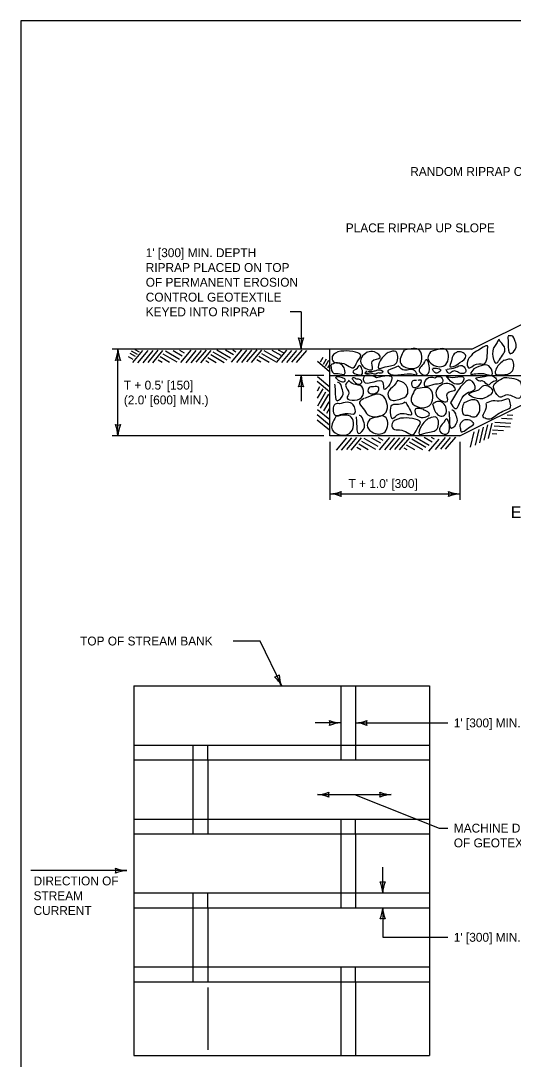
# Model space of a CAD drawing. Extents: x 49991.4 to 50021, y 49987.6 to 50011.4.
# Drawn here: x 50000.34 to 50003.67, y 50004.24 to 50011.26 of the extents above; entities that cross this region are included whole.
import ezdxf

# ---------------------------------------------------------------- set-up
doc = ezdxf.new("R2010")
doc.units = 0
for name, color, linetype in [('Level 1', 7, 'Continuous'), ('Level 2', 7, 'Continuous'), ('Level 3', 7, 'Continuous'), ('Level 4', 7, 'Continuous')]:
    doc.layers.add(name, color=color, linetype=linetype)

msp = doc.modelspace()

# ---------------------------------------------------------------- linework, layer by layer
at = {"layer": 'Level 1'}
for p, q in [((50003.3042, 50008.4558), (50006.7558, 50010.1815)), ((50003.3845, 50009.0417), (50005.7004, 50010.1996)), ((50003.6281, 50009.1282), (50003.6283, 50009.1231)), ((50003.6482, 50009.1332), (50003.6298, 50009.1332)), ((50003.3845, 50009.0417), (50000.9525, 50009.0417)), ((50001.1249, 50009.0062), (50001.0844, 50009.0296)), ((50001.0925, 50008.9516), (50001.1616, 50009.034)), ((50001.1375, 50009.0226), (50001.1098, 50009.0386)), ((50001.128, 50008.9503), (50001.1972, 50009.0327)), ((50001.162, 50008.9503), (50001.2313, 50009.0327)), ((50001.1961, 50008.9528), (50001.2653, 50009.0355)), ((50001.2274, 50008.9503), (50001.2968, 50009.0327)), ((50001.4086, 50008.9731), (50001.314, 50009.0278)), ((50001.4276, 50008.9957), (50001.3667, 50009.0309)), ((50001.4436, 50009.0149), (50001.411, 50009.0336)), ((50001.4176, 50008.952), (50001.487, 50009.0344)), ((50001.4531, 50008.9507), (50001.5225, 50009.0332)), ((50001.4874, 50008.9507), (50001.5565, 50009.0332)), ((50001.5214, 50008.9534), (50001.5905, 50009.0358)), ((50001.5528, 50008.9507), (50001.6219, 50009.0332)), ((50001.7307, 50008.9679), (50001.6359, 50009.0226)), ((50001.7543, 50008.9809), (50001.6616, 50009.0344)), ((50001.7733, 50009.0036), (50001.7198, 50009.0344)), ((50001.7602, 50008.9542), (50001.8293, 50009.0366)), ((50001.7893, 50009.0227), (50001.7688, 50009.0344)), ((50001.7957, 50008.9528), (50001.8648, 50009.0355)), ((50001.8297, 50008.9528), (50001.8988, 50009.0355)), ((50001.8637, 50008.9555), (50001.9331, 50009.0379)), ((50001.8952, 50008.9528), (50001.9644, 50009.0355)), ((50002.0764, 50008.9757), (50001.9816, 50009.0304)), ((50002.0953, 50008.9983), (50002.0342, 50009.0336)), ((50002.0643, 50008.9524), (50002.1334, 50009.0348)), ((50002.1113, 50009.0175), (50002.0788, 50009.0362)), ((50002.0999, 50008.9511), (50002.169, 50009.0336)), ((50002.1338, 50008.9511), (50002.203, 50009.0336)), ((50002.1678, 50008.9538), (50002.2371, 50009.0362)), ((50002.1992, 50008.9511), (50002.2686, 50009.0336)), ((50002.4254, 50008.8642), (50002.4254, 50009.0417)), ((50003.556, 50009.0864), (50003.5296, 50009.046)), ((50001.0954, 50008.9715), (50001.064, 50008.9898)), ((50001.111, 50008.9922), (50001.0749, 50009.0132)), ((50001.2914, 50008.9516), (50001.2637, 50008.9675)), ((50001.3421, 50008.9519), (50001.2776, 50008.9891)), ((50001.3926, 50008.9542), (50001.298, 50009.0089)), ((50001.6061, 50008.9507), (50001.5858, 50008.9624)), ((50001.6573, 50008.9507), (50001.5996, 50008.9839)), ((50001.7117, 50008.9507), (50001.6199, 50009.0036)), ((50001.9592, 50008.9542), (50001.9315, 50008.9702)), ((50002.0148, 50008.9515), (50001.9453, 50008.9917)), ((50002.0604, 50008.9567), (50001.9656, 50009.0114)), ((50002.3415, 50008.9599), (50002.4239, 50008.8908)), ((50002.3614, 50008.957), (50002.3797, 50008.9884)), ((50002.3821, 50008.9414), (50002.4031, 50008.9775)), ((50002.3961, 50008.9275), (50002.4195, 50008.968)), ((50003.389, 50009.0094), (50003.3812, 50008.9977)), ((50002.4125, 50008.9149), (50002.4254, 50008.9372)), ((50002.3402, 50008.825), (50002.4226, 50008.7556)), ((50002.3427, 50008.8563), (50002.4254, 50008.7871)), ((50002.4254, 50008.4558), (50002.4254, 50008.8642)), ((50002.3415, 50008.761), (50002.3574, 50008.7887)), ((50002.3418, 50008.7103), (50002.379, 50008.7748)), ((50002.3441, 50008.6598), (50002.3988, 50008.7544)), ((50003.2877, 50008.7575), (50003.2405, 50008.679)), ((50002.363, 50008.6438), (50002.4177, 50008.7384)), ((50002.3856, 50008.6248), (50002.4208, 50008.6857)), ((50002.3419, 50008.6348), (50002.4243, 50008.5654)), ((50002.4048, 50008.6088), (50002.4235, 50008.6414)), ((50002.3406, 50008.5993), (50002.4231, 50008.5299)), ((50002.3406, 50008.565), (50002.4231, 50008.4959)), ((50003.4689, 50008.4262), (50003.4939, 50008.5312)), ((50003.4982, 50008.438), (50003.5232, 50008.5426)), ((50003.65, 50008.5395), (50003.5408, 50008.546)), ((50003.6568, 50008.5683), (50003.5865, 50008.5726)), ((50003.6626, 50008.5925), (50003.6251, 50008.5949)), ((50003.3767, 50008.3789), (50003.4019, 50008.4835)), ((50003.4091, 50008.3937), (50003.4341, 50008.4984)), ((50003.4396, 50008.4087), (50003.4646, 50008.5136)), ((50003.5548, 50008.4679), (50003.5228, 50008.4699)), ((50003.6, 50008.4907), (50003.5255, 50008.4953)), ((50003.6442, 50008.5153), (50003.5352, 50008.5219)), ((50003.3042, 50008.4558), (50002.4254, 50008.4558)), ((50002.4711, 50008.3601), (50002.5402, 50008.4425)), ((50002.505, 50008.3601), (50002.5744, 50008.4425)), ((50002.5393, 50008.3626), (50002.6084, 50008.445)), ((50002.5705, 50008.3601), (50002.6398, 50008.4425)), ((50002.6851, 50008.3617), (50002.6207, 50008.3989)), ((50002.7357, 50008.364), (50002.641, 50008.4187)), ((50002.7518, 50008.3829), (50002.657, 50008.4376)), ((50002.7706, 50008.4055), (50002.7097, 50008.4407)), ((50002.7867, 50008.4247), (50002.7541, 50008.4434)), ((50002.7607, 50008.3618), (50002.83, 50008.4442)), ((50002.7963, 50008.3605), (50002.8656, 50008.443)), ((50002.8304, 50008.3605), (50002.8995, 50008.443)), ((50002.8644, 50008.3632), (50002.9335, 50008.4456)), ((50002.8959, 50008.3605), (50002.965, 50008.443)), ((50003.0003, 50008.3605), (50002.9428, 50008.3937)), ((50003.0549, 50008.3605), (50002.9631, 50008.4134)), ((50003.0737, 50008.3777), (50002.9791, 50008.4324)), ((50003.0974, 50008.3907), (50003.0046, 50008.4442)), ((50003.1163, 50008.4134), (50003.0628, 50008.4442)), ((50003.1624, 50008.4341), (50003.0933, 50008.3516)), ((50003.1323, 50008.4325), (50003.1119, 50008.4442)), ((50003.1388, 50008.3626), (50003.208, 50008.445)), ((50003.1749, 50008.3653), (50003.242, 50008.445)), ((50003.2068, 50008.3653), (50003.2761, 50008.4477)), ((50002.6346, 50008.3613), (50002.6069, 50008.3773)), ((50002.9491, 50008.3605), (50002.9288, 50008.3722)), ((50001.0997, 50006.7648), (50003.0997, 50006.7648)), ((50001.0997, 50006.7648), (50001.0997, 50004.2648)), ((50002.5997, 50006.7648), (50002.5997, 50006.2648)), ((50003.0997, 50006.7648), (50003.0997, 50004.2648)), ((50001.0997, 50006.2648), (50003.0997, 50006.2648)), ((50001.5997, 50006.2648), (50001.5997, 50005.7648)), ((50001.0997, 50005.7648), (50003.0997, 50005.7648)), ((50002.5997, 50005.7648), (50002.5997, 50005.2648)), ((50001.0997, 50005.2648), (50003.0997, 50005.2648)), ((50001.5997, 50005.2648), (50001.5997, 50004.7648)), ((50001.0997, 50004.7648), (50003.0997, 50004.7648)), ((50002.5997, 50004.7648), (50002.5997, 50004.2648)), ((50001.0997, 50004.2648), (50003.0997, 50004.2648))]:
    msp.add_line(p, q, dxfattribs=at)
msp.add_lwpolyline([(50008.6146, 50011.2628), (50000.3356, 50011.2628), (50000.3356, 50000.0624), (50008.6146, 50000.0624)], close=True, dxfattribs=at)
msp.add_lwpolyline([(50002.4254, 50008.8642), (50004.0986, 50008.8642), (50004.0986, 50008.8642)], dxfattribs=at)
for points in [[(50003.5284, 50009.0453), (50003.5322, 50008.9714), (50003.5485, 50008.9477), (50003.5719, 50008.9707), (50003.609, 50009.0442), (50003.5754, 50009.0964)], [(50003.5754, 50009.0964), (50003.5689, 50009.1065), (50003.556, 50009.0864)], [(50003.6283, 50009.1231), (50003.6314, 50009.0797), (50003.6447, 50009.0112), (50003.6849, 50009.0547), (50003.6781, 50009.0948), (50003.6533, 50009.1332), (50003.6482, 50009.1332)], [(50002.4994, 50009.0288), (50002.442, 50008.9918), (50002.4498, 50008.9567), (50002.4936, 50008.9499), (50002.5455, 50008.9312), (50002.5832, 50008.9167), (50002.6109, 50008.9571), (50002.6342, 50009.002), (50002.5803, 50009.0262), (50002.5006, 50009.0288)], [(50002.6777, 50009.0211), (50002.6397, 50008.986), (50002.6408, 50008.9362), (50002.7128, 50008.9079), (50002.7111, 50008.9606), (50002.7658, 50008.9848), (50002.7264, 50009.0235), (50002.6789, 50009.0219)], [(50002.8199, 50009.0214), (50002.7663, 50008.9641), (50002.7541, 50008.9133), (50002.8003, 50008.9218), (50002.8756, 50008.9496), (50002.8706, 50009.0262), (50002.8222, 50009.02)], [(50002.9287, 50009.0356), (50002.9042, 50008.9452), (50003.0226, 50008.9233), (50003.0334, 50009.0319), (50002.9299, 50009.036)], [(50003.1068, 50009.0237), (50003.0886, 50008.9829), (50003.1201, 50008.9382), (50003.2093, 50008.9387), (50003.2171, 50009.0335), (50003.1068, 50009.0241)], [(50003.2892, 50009.0254), (50003.2605, 50009.0043), (50003.2472, 50008.9624), (50003.2396, 50008.9222), (50003.2585, 50008.9241), (50003.3046, 50008.9508), (50003.3447, 50008.9968), (50003.3275, 50009.0179), (50003.2892, 50009.0235)], [(50003.3812, 50008.9977), (50003.3558, 50008.9594), (50003.3624, 50008.9161), (50003.4159, 50008.9411), (50003.4728, 50008.9444), (50003.4893, 50008.9995), (50003.4925, 50009.0542)], [(50003.4925, 50009.0542), (50003.4927, 50009.0581), (50003.4308, 50009.0364), (50003.3877, 50009.0094)], [(50002.4318, 50008.9347), (50002.4525, 50008.8783), (50002.481, 50008.8779), (50002.5242, 50008.8725), (50002.5104, 50008.9322), (50002.4655, 50008.9494), (50002.4337, 50008.9353)], [(50003.0635, 50008.9496), (50003.0322, 50008.8883), (50003.0752, 50008.8663), (50003.0982, 50008.9047), (50003.0752, 50008.9694), (50003.0612, 50008.9496)], [(50003.6041, 50008.9679), (50003.5508, 50008.9106), (50003.5451, 50008.8754), (50003.5845, 50008.8683), (50003.6598, 50008.8961), (50003.6548, 50008.9727), (50003.6067, 50008.9664)], [(50002.6121, 50008.9114), (50002.5808, 50008.8878), (50002.6147, 50008.87), (50002.6426, 50008.8711), (50002.6238, 50008.9312), (50002.61, 50008.9114)], [(50002.7412, 50008.8508), (50002.6597, 50008.859), (50002.6568, 50008.8202), (50002.7861, 50008.8157), (50002.7925, 50008.7723), (50002.8449, 50008.8434), (50002.7412, 50008.8508)], [(50002.682, 50008.893), (50002.7212, 50008.893), (50002.7433, 50008.9004), (50002.772, 50008.9004), (50002.7836, 50008.8892), (50002.7786, 50008.881), (50002.7541, 50008.881), (50002.7301, 50008.8725), (50002.7068, 50008.8783), (50002.6867, 50008.8783), (50002.6649, 50008.8783), (50002.6758, 50008.895)], [(50002.8874, 50008.9278), (50002.832, 50008.905), (50002.8167, 50008.8954), (50002.8225, 50008.8819), (50002.8644, 50008.8667), (50002.9473, 50008.8752), (50002.989, 50008.8729), (50003.0139, 50008.8687), (50003.0003, 50008.8954), (50002.9296, 50008.8993), (50002.8874, 50008.9261)], [(50003.1208, 50008.9132), (50003.146, 50008.9132), (50003.1747, 50008.9), (50003.1619, 50008.8876), (50003.1479, 50008.8795), (50003.1258, 50008.8934), (50003.1196, 50008.9101)], [(50003.2185, 50008.9078), (50003.2751, 50008.9186), (50003.3194, 50008.931), (50003.3419, 50008.9078), (50003.3419, 50008.8861), (50003.3108, 50008.8775), (50003.2821, 50008.8915), (50003.2534, 50008.8915), (50003.2333, 50008.8775), (50003.2123, 50008.9047)], [(50003.3995, 50008.9089), (50003.3772, 50008.8767), (50003.4528, 50008.8783), (50003.5224, 50008.869), (50003.5099, 50008.9187), (50003.3995, 50008.9094)], [(50002.4576, 50008.8058), (50002.4608, 50008.7622), (50002.474, 50008.6937), (50002.5143, 50008.7372), (50002.5074, 50008.7773), (50002.4826, 50008.8157), (50002.4776, 50008.8157)], [(50002.4667, 50008.8473), (50002.5022, 50008.8226), (50002.5286, 50008.8265), (50002.5286, 50008.8362), (50002.5098, 50008.8488), (50002.4731, 50008.8539), (50002.4638, 50008.8508), (50002.4638, 50008.8467)], [(50002.551, 50008.8265), (50002.5319, 50008.7977), (50002.5527, 50008.7442), (50002.5414, 50008.7118), (50002.5929, 50008.6964), (50002.6484, 50008.729), (50002.6408, 50008.7902), (50002.5873, 50008.8055), (50002.551, 50008.8323)], [(50002.5747, 50008.8447), (50002.599, 50008.8143), (50002.6289, 50008.8061), (50002.6419, 50008.8217), (50002.6263, 50008.8376), (50002.6019, 50008.842), (50002.5901, 50008.8486), (50002.5751, 50008.8457)], [(50002.8838, 50008.8323), (50002.8607, 50008.796), (50002.8187, 50008.7501), (50002.8303, 50008.7042), (50002.901, 50008.7042), (50002.9488, 50008.7347), (50002.9353, 50008.8055), (50002.8857, 50008.8304)], [(50003.01, 50008.8304), (50002.9812, 50008.8227), (50002.9851, 50008.7882), (50003.0271, 50008.7941), (50003.0425, 50008.8323), (50003.0195, 50008.8304)], [(50003.1359, 50008.8492), (50003.08, 50008.8417), (50003.0679, 50008.7909), (50003.114, 50008.7993), (50003.1892, 50008.8274), (50003.1753, 50008.8554), (50003.1359, 50008.8492)], [(50003.1865, 50008.805), (50003.1484, 50008.7698), (50003.1495, 50008.72), (50003.2217, 50008.6917), (50003.2198, 50008.7445), (50003.2745, 50008.7687), (50003.2351, 50008.8075), (50003.1877, 50008.8058)], [(50003.2132, 50008.857), (50003.2202, 50008.85), (50003.2659, 50008.8086), (50003.3271, 50008.8253), (50003.3298, 50008.8515), (50003.2717, 50008.8519), (50003.2132, 50008.857)], [(50003.2409, 50008.6781), (50003.273, 50008.6399), (50003.3447, 50008.7407), (50003.4076, 50008.7747), (50003.3749, 50008.8316), (50003.3179, 50008.7964), (50003.2877, 50008.7589)], [(50003.4117, 50008.8488), (50003.4714, 50008.857), (50003.5393, 50008.8531), (50003.5513, 50008.8314), (50003.5242, 50008.8197), (50003.497, 50008.7988), (50003.4605, 50008.8263), (50003.4392, 50008.8263), (50003.4097, 50008.8453)], [(50003.6037, 50008.8507), (50003.5322, 50008.7883), (50003.5552, 50008.736), (50003.5758, 50008.7179), (50003.6123, 50008.7308), (50003.6613, 50008.7222), (50003.7082, 50008.7113), (50003.7212, 50008.7524), (50003.7141, 50008.8179), (50003.6037, 50008.8507)], [(50002.6561, 50008.7079), (50002.6256, 50008.6831), (50002.6503, 50008.6409), (50002.6828, 50008.5989), (50002.8053, 50008.6161), (50002.7785, 50008.729), (50002.66, 50008.7079)], [(50002.7174, 50008.7882), (50002.6906, 50008.7825), (50002.6847, 50008.7538), (50002.7537, 50008.7597), (50002.7537, 50008.7844), (50002.721, 50008.7882)], [(50003.0033, 50008.7715), (50002.9788, 50008.6812), (50003.0972, 50008.6593), (50003.108, 50008.7679), (50003.0045, 50008.7719)], [(50003.4052, 50008.7579), (50003.3647, 50008.7359), (50003.4022, 50008.7136), (50003.4741, 50008.7122), (50003.5244, 50008.7649), (50003.4673, 50008.7965), (50003.4327, 50008.7676), (50003.4052, 50008.7579)], [(50002.4897, 50008.6735), (50002.4609, 50008.6696), (50002.4592, 50008.5969), (50002.528, 50008.6066), (50002.5949, 50008.6085), (50002.5834, 50008.6659), (50002.4878, 50008.6715)], [(50002.9334, 50008.6831), (50002.8894, 50008.6676), (50002.8455, 50008.664), (50002.8494, 50008.5742), (50002.8913, 50008.6027), (50002.9756, 50008.5989), (50002.9393, 50008.6831)], [(50003.1193, 50008.6727), (50003.14, 50008.6163), (50003.1685, 50008.5915), (50003.2002, 50008.5952), (50003.1982, 50008.6704), (50003.1533, 50008.6874), (50003.1213, 50008.6735)], [(50003.2405, 50008.679), (50003.2404, 50008.6788), (50003.2409, 50008.6781)], [(50003.3315, 50008.68), (50003.3206, 50008.6382), (50003.3341, 50008.5969), (50003.3577, 50008.5958), (50003.3888, 50008.5843), (50003.4194, 50008.5921), (50003.4228, 50008.6926), (50003.3304, 50008.6788)], [(50003.4795, 50008.6754), (50003.4759, 50008.627), (50003.4624, 50008.5817), (50003.4667, 50008.5804)], [(50003.6455, 50008.6691), (50003.6348, 50008.7038), (50003.5863, 50008.6921), (50003.5276, 50008.6921), (50003.481, 50008.6773)], [(50002.4658, 50008.586), (50002.4414, 50008.4956), (50002.5597, 50008.4738), (50002.5705, 50008.5824), (50002.467, 50008.5864)], [(50002.6956, 50008.5684), (50002.6773, 50008.5277), (50002.7088, 50008.4829), (50002.7982, 50008.4835), (50002.8061, 50008.5782), (50002.6956, 50008.5688)], [(50003.0597, 50008.6333), (50003.0023, 50008.6352), (50003.0175, 50008.5894), (50003.0999, 50008.6027), (50003.0577, 50008.6313)], [(50003.2304, 50008.6202), (50003.2335, 50008.5766), (50003.2468, 50008.5081), (50003.287, 50008.5516), (50003.2802, 50008.5917), (50003.2552, 50008.6301), (50003.2503, 50008.6301)], [(50003.4667, 50008.5804), (50003.4975, 50008.5704), (50003.583, 50008.6169), (50003.6481, 50008.6605), (50003.6455, 50008.6691)], [(50002.6031, 50008.5837), (50002.6062, 50008.5403), (50002.6194, 50008.4718), (50002.6596, 50008.5153), (50002.6527, 50008.5554), (50002.6279, 50008.5938), (50002.623, 50008.5938)], [(50002.9031, 50008.5755), (50002.8456, 50008.5386), (50002.8535, 50008.5035), (50002.8972, 50008.4966), (50002.9491, 50008.4778), (50002.9869, 50008.4634), (50003.0146, 50008.5038), (50003.0378, 50008.5488), (50002.9839, 50008.573), (50002.9042, 50008.5755)], [(50003.0952, 50008.5757), (50003.0417, 50008.5184), (50003.0296, 50008.4676), (50003.0757, 50008.4761), (50003.151, 50008.504), (50003.146, 50008.5805), (50003.0976, 50008.5743)], [(50003.1994, 50008.5499), (50003.1681, 50008.4886), (50003.2111, 50008.4665), (50003.2339, 50008.505), (50003.2111, 50008.5696), (50003.1972, 50008.5499)], [(50003.3373, 50008.5652), (50003.3056, 50008.5352), (50003.3092, 50008.5024)], [(50003.3092, 50008.5024), (50003.3107, 50008.4884), (50003.3741, 50008.5169), (50003.3959, 50008.5434), (50003.3944, 50008.5446)], [(50003.3944, 50008.5446), (50003.3791, 50008.5587), (50003.3408, 50008.5652)]]:
    msp.add_spline(points, degree=3, dxfattribs=at)
at = {"layer": 'Level 3'}
for p, q in [((50002.2307, 50009.2943), (50002.1578, 50009.2943)), ((50002.2307, 50009.2943), (50002.2307, 50009.0417)), ((50000.9925, 50008.4558), (50000.9925, 50009.0417)), ((50002.3854, 50008.8642), (50002.1907, 50008.8642)), ((50002.2307, 50008.8642), (50002.2307, 50008.6907)), ((50002.3854, 50008.4558), (50000.9525, 50008.4558)), ((50002.4254, 50008.4158), (50002.4254, 50008.0234)), ((50003.3042, 50008.4158), (50003.3042, 50008.0234)), ((50002.4254, 50008.0634), (50003.3042, 50008.0634)), ((50001.9542, 50007.0683), (50001.7711, 50007.0683)), ((50002.0997, 50006.7648), (50001.9542, 50007.0683)), ((50002.4997, 50006.5148), (50002.3262, 50006.5148)), ((50002.5997, 50006.5148), (50003.2233, 50006.5148)), ((50002.3428, 50006.0297), (50002.8393, 50006.0297)), ((50002.591, 50006.0297), (50003.1651, 50005.8032)), ((50003.1651, 50005.8032), (50003.2233, 50005.8032)), ((50001.0526, 50005.5159), (50000.404, 50005.5159)), ((50002.7825, 50005.3648), (50002.7825, 50005.5382)), ((50002.7825, 50005.2648), (50002.7825, 50005.0648)), ((50002.7825, 50005.0648), (50003.2233, 50005.0648)), ((50001.5997, 50004.7248), (50001.5997, 50004.3048))]:
    msp.add_line(p, q, dxfattribs=at)
for centre, radius, start, end in [((50002.2307, 50009.1699), 0.0548, 252.13882, 287.86118), ((50001.998, 50009.0302), 0.233, 2.82731, 22.07716), ((50002.4528, 50009.0325), 0.2223, 157.45601, 177.63952), ((50000.7703, 50009.0508), 0.2223, 337.45601, 357.63952), ((50001.2252, 50009.0531), 0.233, 182.82731, 202.07716), ((50000.9925, 50008.9134), 0.0548, 72.13882, 107.86118), ((50002.0086, 50008.8733), 0.2223, 337.45601, 357.63952), ((50002.4634, 50008.8756), 0.233, 182.82731, 202.07716), ((50002.2307, 50008.7359), 0.0548, 72.13882, 107.86118), ((50000.9925, 50008.584), 0.0548, 252.13882, 287.86118), ((50000.7597, 50008.4443), 0.233, 2.82731, 22.07716), ((50001.2146, 50008.4466), 0.2223, 157.45601, 177.63952), ((50002.4139, 50008.2961), 0.233, 272.82731, 292.07716), ((50002.4162, 50007.8412), 0.2223, 67.45601, 87.63952), ((50002.5536, 50008.0634), 0.0548, 162.13882, 197.86118), ((50003.3133, 50008.2855), 0.2223, 247.45601, 267.63952), ((50003.1759, 50008.0634), 0.0548, 342.13882, 17.86118), ((50003.3156, 50007.8306), 0.233, 92.82731, 112.07716), ((50002.0443, 50006.8804), 0.0548, 277.75113, 313.47349), ((50001.8948, 50006.6538), 0.233, 28.43962, 47.68947), ((50002.3039, 50006.8526), 0.2223, 183.06832, 203.25183), ((50002.5088, 50006.7369), 0.2223, 247.45601, 267.63952), ((50002.3715, 50006.5148), 0.0548, 342.13882, 17.86118), ((50002.5112, 50006.2821), 0.233, 92.82731, 112.07716), ((50002.5882, 50006.7475), 0.233, 272.82731, 292.07716), ((50002.5905, 50006.2927), 0.2223, 67.45601, 87.63952), ((50002.7279, 50006.5148), 0.0548, 162.13882, 197.86118), ((50002.3313, 50006.2624), 0.233, 272.82731, 292.07716), ((50002.3336, 50005.8075), 0.2223, 67.45601, 87.63952), ((50002.471, 50006.0297), 0.0548, 162.13882, 197.86118), ((50002.8484, 50006.2518), 0.2223, 247.45601, 267.63952), ((50002.7111, 50006.0297), 0.0548, 342.13882, 17.86118), ((50002.8508, 50005.797), 0.233, 92.82731, 112.07716), ((50001.0617, 50005.7381), 0.2223, 247.45601, 267.63952), ((50000.9243, 50005.5159), 0.0548, 342.13882, 17.86118), ((50001.064, 50005.2832), 0.233, 92.82731, 112.07716), ((50002.7825, 50005.493), 0.0548, 252.13882, 287.86118), ((50002.5497, 50005.3533), 0.233, 2.82731, 22.07716), ((50003.0046, 50005.3556), 0.2223, 157.45601, 177.63952), ((50002.5603, 50005.2739), 0.2223, 337.45601, 357.63952), ((50003.0152, 50005.2763), 0.233, 182.82731, 202.07716), ((50002.7825, 50005.1366), 0.0548, 72.13882, 107.86118)]:
    msp.add_arc(centre, radius, start, end, dxfattribs=at)
at = {"layer": 'Level 4'}
for p, q in [((50002.4997, 50006.7648), (50002.4997, 50006.2648)), ((50001.0997, 50006.3648), (50003.0997, 50006.3648)), ((50001.4997, 50006.3648), (50001.4997, 50005.7648)), ((50001.5997, 50006.2648), (50001.5997, 50006.3648)), ((50001.0997, 50005.8648), (50003.0997, 50005.8648)), ((50002.4997, 50005.8648), (50002.4997, 50005.2648)), ((50002.5997, 50005.7648), (50002.5997, 50005.8648)), ((50001.0997, 50005.3648), (50003.0997, 50005.3648)), ((50001.4997, 50005.3648), (50001.4997, 50004.7648)), ((50001.5997, 50005.2648), (50001.5997, 50005.3648)), ((50001.0997, 50004.8648), (50003.0997, 50004.8648)), ((50002.4997, 50004.8648), (50002.4997, 50004.2648)), ((50002.5997, 50004.7648), (50002.5997, 50004.8648))]:
    msp.add_line(p, q, dxfattribs=at)

# ---------------------------------------------------------------- texts
at = {"layer": 'Level 2'}
for s, height, p in [('RANDOM RIPRAP CLASS I,II OR III', 0.06, (50002.9688, 50010.2134)), ('PLACE RIPRAP UP SLOPE', 0.06, (50002.5329, 50009.8323)), ("1' [300] MIN. DEPTH", 0.06, (50001.1805, 50009.6643)), ('RIPRAP PLACED ON TOP', 0.06, (50001.1805, 50009.5643)), ('OF PERMANENT EROSION', 0.06, (50001.1805, 50009.4643)), ('CONTROL GEOTEXTILE', 0.06, (50001.1805, 50009.3643)), ('KEYED INTO RIPRAP', 0.06, (50001.1805, 50009.2643)), ("T + 0.5' [150]", 0.06, (50001.0325, 50008.7688)), ("(2.0' [600] MIN.)", 0.06, (50001.0325, 50008.6688)), ("T + 1.0' [300]", 0.06, (50002.5516, 50008.1034)), ('EMBANKMENT PROTECTION', 0.08, (50003.6484, 50007.8995)), ('TOP OF STREAM BANK', 0.06, (50000.7367, 50007.0383)), ("1' [300] MIN. OVERLAP", 0.06, (50003.2633, 50006.4845)), ('MACHINE DIRECTION ', 0.06, (50003.2633, 50005.7732)), ('OF GEOTEXTILE', 0.06, (50003.2633, 50005.6732)), ('DIRECTION OF', 0.06, (50000.4221, 50005.4159)), ('STREAM ', 0.06, (50000.4221, 50005.3159)), ('CURRENT', 0.06, (50000.4221, 50005.2159)), ("1' [300] MIN. OVERLAP", 0.06, (50003.2633, 50005.0348))]:
    msp.add_text(s, height=height, dxfattribs=at).set_placement(p)

doc.saveas('drawing.dxf')
